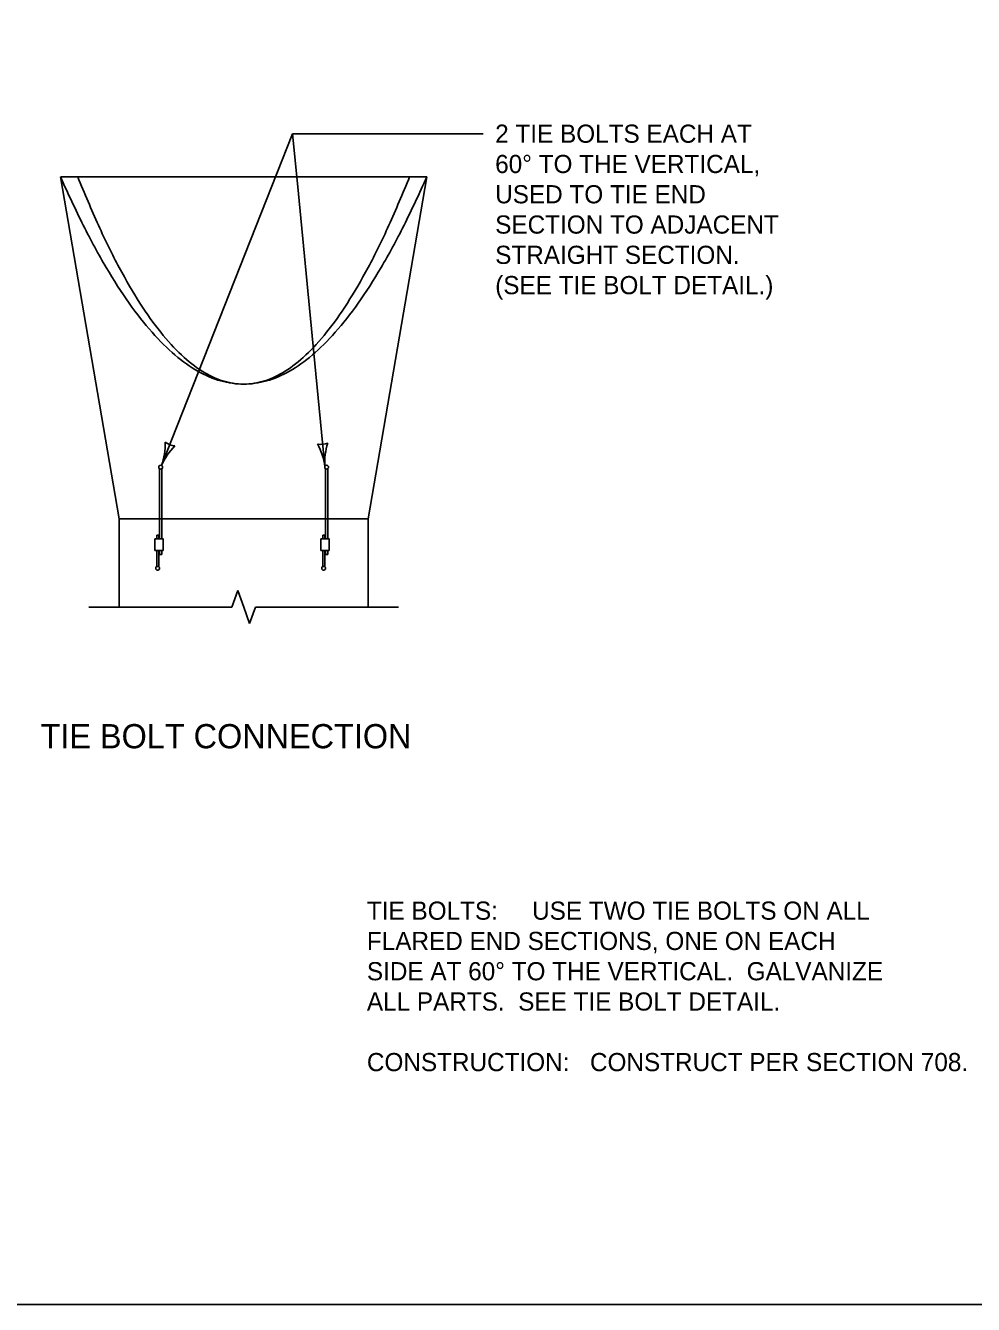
# Model space of a CAD drawing. Extents: x 49991.4 to 50022.1, y 49985 to 50011.4.
# Drawn here: x 50008.666 to 50011.795, y 49987.799 to 49992.021 of the extents above; entities that cross this region are included whole.
import ezdxf

# ---------------------------------------------------------------- set-up
doc = ezdxf.new("R2010")
doc.units = 0
for name, color, linetype in [('Level 1', 7, 'Continuous'), ('Level 2', 7, 'Continuous'), ('Level 3', 7, 'Continuous'), ('Level 6', 7, 'Continuous')]:
    doc.layers.add(name, color=color, linetype=linetype)

msp = doc.modelspace()

# ---------------------------------------------------------------- linework, layer by layer
at = {"layer": 'Level 1'}
for p, q in [((50008.7813, 49991.5224), (50008.9754, 49990.3923)), ((50009.9914, 49991.5224), (50008.7833, 49991.5224)), ((50009.7973, 49990.3923), (50009.9914, 49991.5224)), ((50009.1089, 49990.3264), (50009.1089, 49990.5582)), ((50009.1162, 49990.3264), (50009.1162, 49990.5583)), ((50009.6569, 49990.3264), (50009.6569, 49990.5582)), ((50009.6642, 49990.3264), (50009.6642, 49990.5583)), ((50008.9754, 49990.3923), (50009.7973, 49990.3923)), ((50008.9754, 49990.3923), (50008.9754, 49990.1015)), ((50009.7973, 49990.3923), (50009.7973, 49990.1015)), ((50009.0993, 49990.3264), (50009.0993, 49990.3393)), ((50009.0993, 49990.3393), (50009.1059, 49990.3393)), ((50009.1059, 49990.3264), (50009.1059, 49990.3393)), ((50009.6473, 49990.3264), (50009.6473, 49990.3393)), ((50009.6473, 49990.3393), (50009.6539, 49990.3393)), ((50009.6539, 49990.3264), (50009.6539, 49990.3393)), ((50009.0993, 49990.2343), (50009.0993, 49990.2883)), ((50009.1059, 49990.2343), (50009.1059, 49990.2883)), ((50009.1089, 49990.2744), (50009.1089, 49990.2883)), ((50009.1089, 49990.2744), (50009.1162, 49990.2744)), ((50009.1162, 49990.2744), (50009.1162, 49990.2883)), ((50009.6473, 49990.2343), (50009.6473, 49990.2883)), ((50009.6539, 49990.2343), (50009.6539, 49990.2883)), ((50009.6569, 49990.2744), (50009.6569, 49990.2883)), ((50009.6569, 49990.2744), (50009.6642, 49990.2744)), ((50009.6642, 49990.2744), (50009.6642, 49990.2883))]:
    msp.add_line(p, q, dxfattribs=at)
for points in [[(49999.3835, 49998.9992), (50016.7501, 49998.9992), (50016.7501, 49987.7988), (49999.3835, 49987.7988)], [(50009.1211, 49990.2883), (50009.0933, 49990.2883), (50009.0933, 49990.3264), (50009.1211, 49990.3264)], [(50009.6689, 49990.2883), (50009.6413, 49990.2883), (50009.6413, 49990.3264), (50009.6689, 49990.3264)]]:
    msp.add_lwpolyline(points, close=True, dxfattribs=at)
for centre in [(50009.1124, 49990.5634), (50009.6603, 49990.5634), (50009.1024, 49990.2294), (50009.6503, 49990.2294)]:
    msp.add_circle(centre, 0.00625, dxfattribs=at)
for points in [[(50008.7813, 49991.5224), (50009.3864, 49990.1525), (50009.9914, 49991.5224)], [(50008.8384, 49991.5224), (50009.3864, 49990.1525), (50009.9343, 49991.5224)]]:
    msp.add_open_spline(points, degree=2, dxfattribs=at)
at = {"layer": 'Level 3'}
for p, q in [((50009.1153, 49990.569), (50009.5481, 49991.6644)), ((50009.5481, 49991.6644), (50009.564, 49991.4998)), ((50009.5481, 49991.6644), (50010.1767, 49991.6644)), ((50009.5641, 49991.4998), (50009.6215, 49990.9061)), ((50009.6216, 49990.9061), (50009.6545, 49990.5657))]:
    msp.add_line(p, q, dxfattribs=at)
for centre, radius, start, end in [((50008.8946, 49990.6438), 0.233, 341.2676, 0.5174), ((50009.3185, 49990.4788), 0.2223, 135.8963, 156.0798), ((50009.1624, 49990.6882), 0.0548, 230.5791, 266.3015), ((50009.6422, 49990.6933), 0.0548, 257.6699, 293.3923), ((50009.424, 49990.5318), 0.233, 8.3584, 27.6083), ((50009.8765, 49990.578), 0.2223, 162.9871, 183.1706)]:
    msp.add_arc(centre, radius, start, end, dxfattribs=at)
at = {"layer": 'Level 6'}
for p, q in [((50009.367, 49990.1563), (50009.3475, 49990.1015)), ((50009.367, 49990.1563), (50009.3864, 49990.1015)), ((50008.8754, 49990.1015), (50009.3475, 49990.1015)), ((50009.3864, 49990.1015), (50009.4058, 49990.0467)), ((50009.4253, 49990.1015), (50009.4058, 49990.0467)), ((50009.4253, 49990.1015), (50009.8973, 49990.1015))]:
    msp.add_line(p, q, dxfattribs=at)

# ---------------------------------------------------------------- texts
at = {"layer": 'Level 2'}
for s, height, p in [('2 TIE BOLTS EACH AT', 0.06, (50010.2167, 49991.6344)), ('60° TO THE VERTICAL,', 0.06, (50010.2167, 49991.5344)), ('USED TO TIE END', 0.06, (50010.2167, 49991.4344)), ('SECTION TO ADJACENT', 0.06, (50010.2167, 49991.3344)), ('STRAIGHT SECTION.', 0.06, (50010.2167, 49991.2344)), ('(SEE TIE BOLT DETAIL.)', 0.06, (50010.2167, 49991.1344)), ('TIE BOLT CONNECTION', 0.08, (50008.7159, 49989.635)), ('TIE BOLTS:', 0.06, (50009.7932, 49989.069)), ('  USE TWO TIE BOLTS ON ALL', 0.06, (50010.294, 49989.069)), ('FLARED END SECTIONS, ONE ON EACH', 0.06, (50009.7932, 49988.969)), ('SIDE AT 60° TO THE VERTICAL.  GALVANIZE', 0.06, (50009.7932, 49988.869)), ('ALL PARTS.  SEE TIE BOLT DETAIL.', 0.06, (50009.7932, 49988.769)), ('CONSTRUCTION:', 0.06, (50009.7932, 49988.569)), ('  CONSTRUCT PER SECTION 708.', 0.06, (50010.485, 49988.569))]:
    msp.add_text(s, height=height, dxfattribs=at).set_placement(p)

doc.saveas('drawing.dxf')
